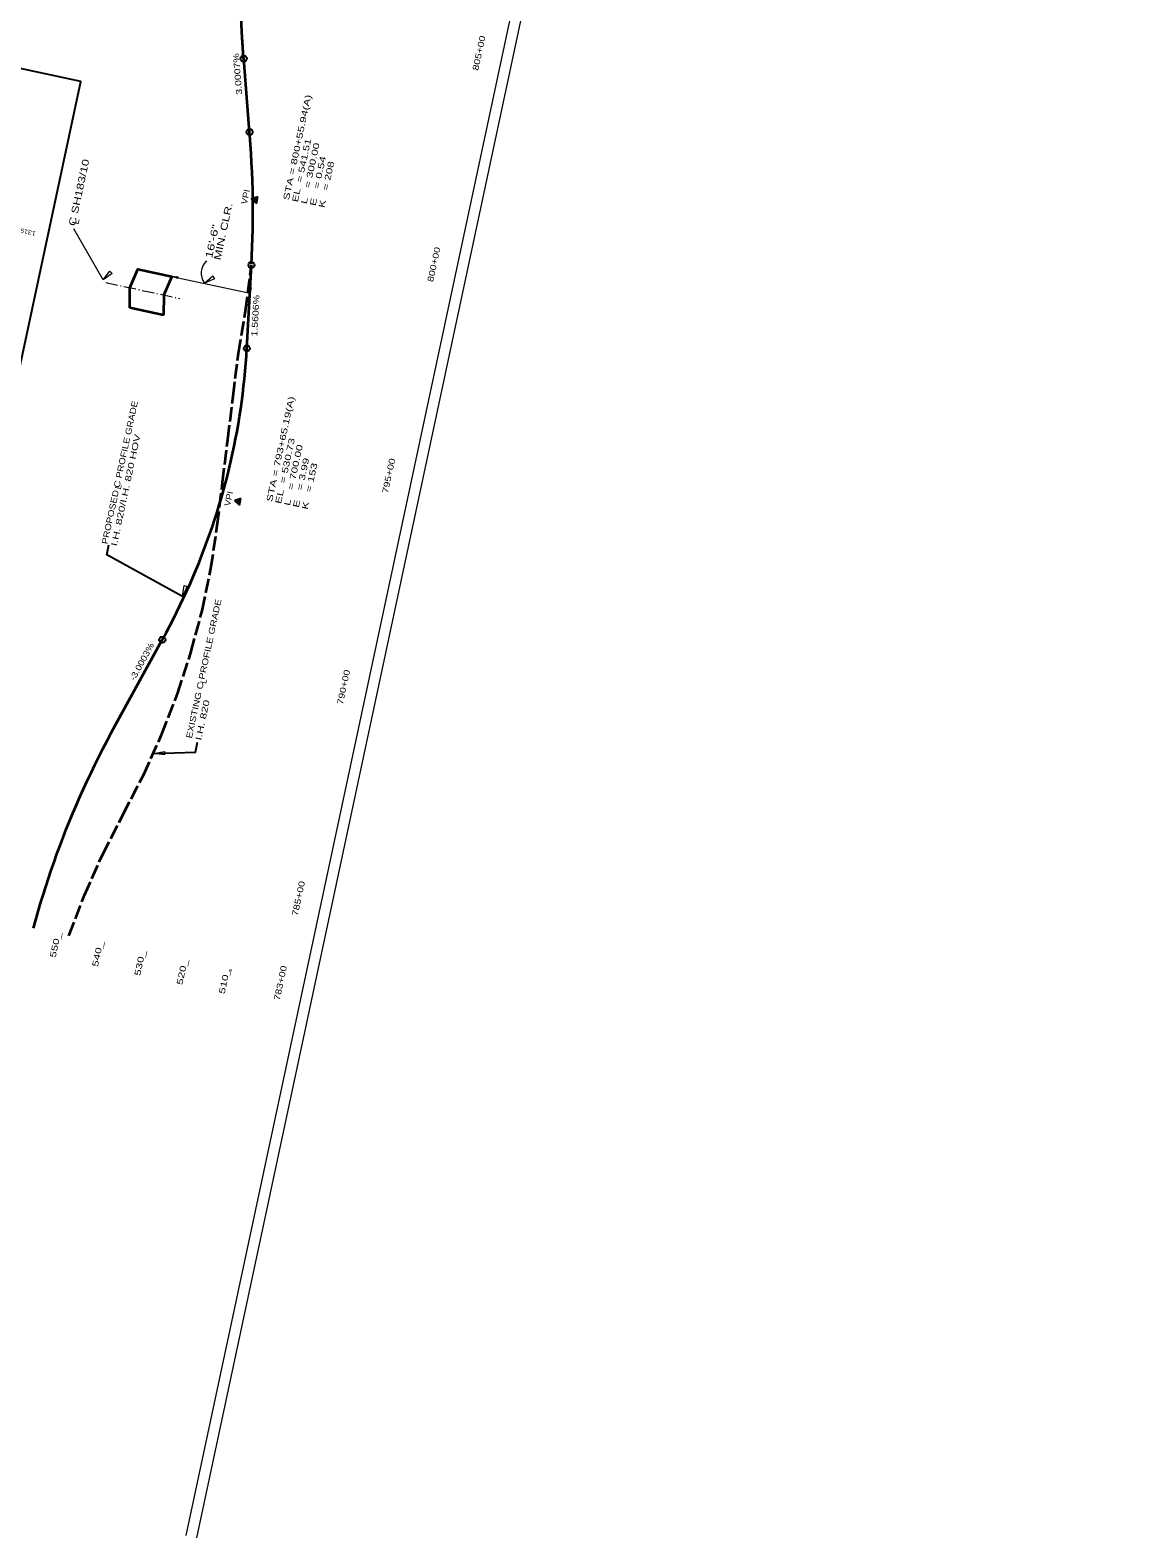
# Model space of a CAD drawing. Extents: x 2363411 to 2369702, y 6977197 to 6988655.
# Drawn here: x 2366546 to 2369126, y 6977197 to 6980686 of the extents above; entities that cross this region are included whole.
import ezdxf
from ezdxf.enums import TextEntityAlignment as Align

# ---------------------------------------------------------------- set-up
doc = ezdxf.new("R2010")
doc.units = 0
doc.header["$LTSCALE"] = 5.6
for name, pattern in [('DOT_DASHED', [7.7, 5, -1.2, 0.3, -1.2]), ('DOTTED', [1.5, 0.3, -1.2]), ('LONG_DASHED', [7.5, 6, -1.5])]:
    doc.linetypes.add(name, pattern=pattern)
for name, color, linetype, lineweight in [('10', 7, 'Continuous', 13), ('44', 7, 'Continuous', 25), ('55', 7, 'Continuous', 35), ('61', 7, 'Continuous', 25), ('63', 7, 'Continuous', 13)]:
    doc.layers.add(name, color=color, linetype=linetype, lineweight=lineweight)

msp = doc.modelspace()

# ---------------------------------------------------------------- linework, layer by layer
at = {"layer": '10'}
for p, q in [((2366907.66, 6977202.711), (2369101.754, 6987471.397)), ((2366932.108, 6977197.487), (2369126.202, 6987466.173))]:
    msp.add_line(p, q, dxfattribs=at)
at = {"layer": '44'}
for p, q in [((2367057.817, 6980295.749), (2367073.214, 6980300.641)), ((2367057.817, 6980295.749), (2367069.749, 6980284.857)), ((2367069.749, 6980284.857), (2367073.214, 6980300.641)), ((2367018.885, 6979597.61), (2367034.239, 6979602.637)), ((2367018.885, 6979597.61), (2367030.912, 6979586.823)), ((2367030.912, 6979586.823), (2367034.239, 6979602.637))]:
    msp.add_line(p, q, dxfattribs=at)
at = {"layer": '44', "linetype": 'DOTTED'}
msp.add_line((2367007.923, 6978510.692), (2367014.768, 6978509.229), dxfattribs=at)
at = {"layer": '44', "lineweight": 35}
for points in [[(2367058.569, 6980143.942), (2367059.53, 6980162.804), (2367060.386, 6980183.494), (2367061.048, 6980204.226), (2367061.513, 6980224.999), (2367061.782, 6980245.816), (2367061.856, 6980266.674), (2367061.735, 6980287.571), (2367061.647, 6980294.871), (2367061.647, 6980294.871), (2367061.261, 6980315.826), (2367060.68, 6980336.824), (2367059.904, 6980357.862), (2367058.932, 6980378.942), (2367057.765, 6980400.065), (2367056.401, 6980421.229), (2367054.843, 6980442.436), (2367054.254, 6980449.843), (2367040.448, 6980619.883)], [(2366554.003, 6978607.681), (2366559.258, 6978627.009), (2366564.708, 6978646.297), (2366570.356, 6978665.542), (2366576.199, 6978684.746), (2366582.236, 6978703.907), (2366588.469, 6978723.028), (2366594.898, 6978742.106), (2366601.522, 6978761.143), (2366608.343, 6978780.137), (2366615.358, 6978799.09), (2366622.568, 6978818), (2366629.977, 6978836.87), (2366637.578, 6978855.697), (2366645.377, 6978874.483), (2366653.37, 6978893.227), (2366661.559, 6978911.93), (2366669.944, 6978930.59), (2366678.525, 6978949.209), (2366687.3, 6978967.785), (2366696.272, 6978986.319), (2366705.438, 6979004.812), (2366714.802, 6979023.264), (2366724.36, 6979041.673), (2366734.114, 6979060.042), (2366744.063, 6979078.367), (2366744.07, 6979078.379), (2366852.178, 6979275.337), (2366852.178, 6979275.337), (2366860.881, 6979291.394), (2366869.391, 6979307.491), (2366877.704, 6979323.632), (2366885.82, 6979339.815), (2366893.742, 6979356.039), (2366901.467, 6979372.304), (2366908.999, 6979388.611), (2366916.334, 6979404.96), (2366923.474, 6979421.351), (2366930.417, 6979437.784), (2366937.165, 6979454.259), (2366943.717, 6979470.775), (2366950.075, 6979487.333), (2366956.237, 6979503.933), (2366962.202, 6979520.575), (2366967.972, 6979537.258), (2366973.547, 6979553.983), (2366978.925, 6979570.75), (2366984.109, 6979587.56), (2366988.984, 6979604.023), (2366988.984, 6979604.023), (2366993.781, 6979620.913), (2366998.381, 6979637.847), (2367002.787, 6979654.822), (2367006.998, 6979671.84), (2367011.012, 6979688.899), (2367014.83, 6979705.998), (2367018.453, 6979723.141), (2367021.88, 6979740.325), (2367025.112, 6979757.551), (2367028.148, 6979774.818), (2367030.989, 6979792.127), (2367033.635, 6979809.479), (2367036.084, 6979826.872), (2367038.338, 6979844.307), (2367040.397, 6979861.783), (2367042.259, 6979879.301), (2367043.926, 6979896.862), (2367045.398, 6979914.464), (2367046.674, 6979932.109), (2367047.732, 6979949.386), (2367058.477, 6980142.155)]]:
    msp.add_lwpolyline(points, dxfattribs=at)
at = {"layer": '44', "linetype": 'LONG_DASHED', "lineweight": 35}
msp.add_lwpolyline([(2366635.948, 6978590.171), (2366671.905, 6978684.75), (2366713.534, 6978778.116), (2366760.933, 6978870.251), (2366808.43, 6978962.364), (2366850.548, 6979055.627), (2366887.19, 6979150.06), (2366918.354, 6979245.663), (2366944.141, 6979342.415), (2366964.45, 6979440.337), (2366979.38, 6979539.409), (2366991.573, 6979639.066), (2367003.766, 6979738.723), (2367015.957, 6979838.379), (2367028.15, 6979938.036), (2367044.822, 6980036.449), (2367058.477, 6980142.155)], dxfattribs=at)
at = {"layer": '44'}
for centre, radius in [((2367040.456, 6980619.882), 7), ((2367054.254, 6980449.843), 7), ((2367066.928, 6980293.738), 1.5), ((2367058.477, 6980142.155), 7), ((2367047.731, 6979949.387), 7), ((2367028.013, 6979595.679), 1.5), ((2366852.178, 6979275.337), 7)]:
    msp.add_circle(centre, radius, dxfattribs=at)
at = {"layer": '44', "lineweight": 35}
msp.add_spline([(2367040.455, 6980619.882), (2367039.634, 6980630.283), (2367038.862, 6980640.673), (2367038.139, 6980651.054), (2367037.463, 6980661.424), (2367036.838, 6980671.783), (2367036.26, 6980682.132), (2367035.73, 6980692.471), (2367035.248, 6980702.8), (2367034.816, 6980713.118), (2367034.432, 6980723.426), (2367034.096, 6980733.723), (2367033.809, 6980744.01), (2367033.571, 6980754.287), (2367033.382, 6980764.553), (2367033.24, 6980774.809), (2367033.147, 6980785.055), (2367033.103, 6980795.29), (2367033.107, 6980805.515), (2367033.159, 6980815.729), (2367033.261, 6980825.933), (2367033.41, 6980836.127), (2367033.609, 6980846.31), (2367033.856, 6980856.483), (2367034.15, 6980866.646), (2367034.495, 6980876.798), (2367034.886, 6980886.94), (2367035.327, 6980897.072), (2367035.817, 6980907.193), (2367036.355, 6980917.303), (2367036.941, 6980927.404), (2367037.575, 6980937.494), (2367038.258, 6980947.574), (2367038.991, 6980957.643), (2367039.772, 6980967.702), (2367040.602, 6980977.751), (2367041.479, 6980987.789), (2367042.404, 6980997.817), (2367043.379, 6981007.834), (2367044.403, 6981017.841), (2367045.473, 6981027.838), (2367046.594, 6981037.824), (2367047.763, 6981047.8), (2367048.98, 6981057.766), (2367050.244, 6981067.722), (2367051.559, 6981077.667), (2367052.921, 6981087.601), (2367054.334, 6981097.525), (2367055.794, 6981107.439), (2367057.3, 6981117.343), (2367058.858, 6981127.236)], degree=3, dxfattribs=at)
at = {"layer": '61', "lineweight": 13}
for p, q in [((2366714.879, 6980107.846), (2366647.03, 6980225.999)), ((2366874.448, 6980116.089), (2367055.781, 6980077.344))]:
    msp.add_line(p, q, dxfattribs=at)
at = {"layer": '61', "linetype": 'DOT_DASHED', "lineweight": 13}
msp.add_line((2366721.225, 6980101.787), (2366892.946, 6980065.096), dxfattribs=at)
at = {"layer": '61', "lineweight": 35}
for p, q in [((2366874.448, 6980116.089), (2366855.838, 6980073.025)), ((2366855.838, 6980073.025), (2366855.223, 6980026.116)), ((2366855.223, 6980026.116), (2366776.6, 6980042.915))]:
    msp.add_line(p, q, dxfattribs=at)
at = {"layer": '61'}
msp.add_lwpolyline([(2366482.339, 6979717.696), (2366663.815, 6980567.032), (2366167.737, 6980673.028), (2365986.261, 6979823.692)], close=True, dxfattribs=at)
at = {"layer": '61', "lineweight": 13}
for points in [[(2366735.809, 6980122.567), (2366714.879, 6980107.846), (2366730.821, 6980128.139)], [(2366973.124, 6980110.502), (2366949.565, 6980100.515), (2366969.42, 6980116.999)], [(2366909.638, 6979398.732), (2366899.034, 6979375.444), (2366902.515, 6979401.014)], [(2366856.895, 6979009.067), (2366831.484, 6979012.073), (2366856.9, 6979016.546)]]:
    msp.add_lwpolyline(points, close=True, dxfattribs=at)
at = {"layer": '61', "lineweight": 35}
msp.add_lwpolyline([(2366776.6, 6980042.915), (2366777.214, 6980089.824), (2366795.824, 6980132.888), (2366874.448, 6980116.089)], dxfattribs=at)
at = {"layer": '61'}
for points in [[(2366899.034, 6979375.444), (2366723.606, 6979472.068), (2366728.44, 6979494.693)], [(2366831.569, 6979012.083), (2366928.919, 6979015.595), (2366933.753, 6979038.219)]]:
    msp.add_lwpolyline(points, dxfattribs=at)
at = {"layer": '61', "lineweight": 13}
msp.add_arc((2366981.737, 6980123.429), 39.498, 133.85546, 215.46011, dxfattribs=at)
at = {"layer": '63'}
for p, q in [((2366887.892, 6980113.149), (2366875.629, 6980115.896)), ((2366887.782, 6980112.661), (2366879.381, 6980114.543)), ((2366888, 6980113.638), (2366880.829, 6980115.244)), ((2366887.673, 6980112.174), (2366882.929, 6980113.236)), ((2366888.111, 6980114.126), (2366883.936, 6980115.06)), ((2366887.564, 6980111.686), (2366885.239, 6980112.207)), ((2366888.219, 6980114.613), (2366886.672, 6980114.96)), ((2366888.296, 6980114.955), (2366887.459, 6980111.217)), ((2367054.183, 6980090.699), (2367058.013, 6980090.608)), ((2367054.534, 6980090.69), (2367054.496, 6980089.105)), ((2367055.033, 6980090.678), (2367054.932, 6980086.403)), ((2367055.533, 6980090.666), (2367055.358, 6980083.317)), ((2367056.033, 6980090.654), (2367055.734, 6980078.092)), ((2367056.533, 6980090.643), (2367056.328, 6980082.034)), ((2367057.033, 6980090.63), (2367056.917, 6980085.769)), ((2367057.532, 6980090.619), (2367057.476, 6980088.237))]:
    msp.add_line(p, q, dxfattribs=at)
for centre, start, end in [((2366887.152, 6980187.163), 260.22176, 270.90781), ((2366855.631, 6980046.395), 63.84859, 74.53464), ((2366983.589, 6980075.478), 1.48009, 12.16614), ((2367127.802, 6980072.046), 165.10692, 175.79297)]:
    msp.add_arc(centre, 72.216, start, end, dxfattribs=at)

# ---------------------------------------------------------------- texts
at = {"layer": '44'}
for s, rotation, width, p in [('805+00', 77.939, 1.3, (2367591.893, 6980631.282)), ('VPI', 77.616, 1.15, (2367051.433, 6980298.716)), ('800+00', 77.939, 1.3, (2367487.412, 6980142.296)), ('795+00', 77.939, 1.3, (2367382.931, 6979653.312)), ('VPI', 78.122, 1.15, (2367012.463, 6979600.456)), ('790+00', 77.939, 1.3, (2367278.451, 6979164.326)), ('785+00', 77.939, 1.3, (2367173.97, 6978675.342)), ('783+00', 77.939, 1.3, (2367132.178, 6978479.748))]:
    msp.add_text(s, height=14, rotation=rotation, dxfattribs=dict(at, width=width)).set_placement(p, align=Align.CENTER)
for s, rotation, width, p in [('3.0007%', 94.642, 1.3, (2367037.088, 6980536.956)), ('STA = 800+55.94(A)', 77.939, 1.45, (2367145.158, 6980291.343)), ('EL  = 541.51', 77.939, 1.4, (2367165.695, 6980286.955)), ('L   = 300.00', 77.939, 1.45, (2367186.232, 6980282.567)), ('E   = 0.54', 77.939, 1.45, (2367206.77, 6980278.179)), ('K   = 208', 77.939, 1.45, (2367227.307, 6980273.791)), ('1.5606%', 86.809, 1.3, (2367071.816, 6979976.683)), ('STA = 793+65.19(A)', 77.939, 1.45, (2367106.243, 6979593.284)), ('EL  = 530.73', 77.939, 1.45, (2367126.78, 6979588.896)), ('L   = 700.00', 77.939, 1.45, (2367147.317, 6979584.508)), ('E   = 3.99', 77.939, 1.45, (2367167.855, 6979580.12)), ('K   = 153', 77.939, 1.45, (2367188.392, 6979575.732)), ('-3.0003%', 61.238, 1.2, (2366787.855, 6979179.052))]:
    msp.add_text(s, height=14, rotation=rotation, dxfattribs=dict(at, width=width)).set_placement(p)
at = {"layer": '44', "width": 1.45}
for s, p in [('  550_', (2366617.709, 6978597.661)), ('  540_', (2366715.507, 6978576.765)), ('  530_', (2366813.303, 6978555.869)), ('  520_', (2366911.101, 6978534.972)), ('  510_', (2367008.897, 6978514.076))]:
    msp.add_text(s, height=14, rotation=77.939, dxfattribs=at).set_placement(p, align=Align.RIGHT)
at = {"layer": '55', "width": 1.25}
msp.add_text('1319', height=10, rotation=167, dxfattribs=at).set_placement((2366542.278, 6980223.276), align=Align.CENTER)
at = {"layer": '61'}
for s, height, width, p in [('C SH183/10', 16, 1.35, (2366666.979, 6980308.483)), ('L', 16, 1.05, (2366659.425, 6980241.494)), ('L', 14, 1.05, (2366757.182, 6979627.87))]:
    msp.add_text(s, height=height, rotation=77.939, dxfattribs=dict(at, width=width)).set_placement(p, align=Align.CENTER)
for s, height, width, p in [('MIN. CLR.', 16, 1.35, (2366986.744, 6980152.633)), ('16\'-6"', 16, 1.45, (2366967.185, 6980156.812)), ('PROPOSED C PROFILE GRADE', 14, 1.2, (2366725.203, 6979495.549)), ('I.H. 820/I.H. 820 HOV', 14, 1.45, (2366746.718, 6979490.952)), ('EXISTING C PROFILE GRADE', 14, 1.25, (2366920.526, 6979046.195)), ('L', 14, 1.05, (2366953.491, 6979172.691)), ('I.H. 820', 14, 1.45, (2366942.041, 6979041.598))]:
    msp.add_text(s, height=height, rotation=77.939, dxfattribs=dict(at, width=width)).set_placement(p)

doc.saveas('drawing.dxf')
